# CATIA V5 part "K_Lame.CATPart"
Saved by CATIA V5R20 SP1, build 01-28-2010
Part number: lame
Bounding box of the stored display mesh (mm): x 0 to 3, y -5 to 5, z 0 to 19.99
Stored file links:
  G:\Khaled_CFAO_2011\SIL\SIL_GR1\mroland\Khaled\CAD_CATIA_Modifie\K_Lame.CATPart
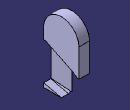
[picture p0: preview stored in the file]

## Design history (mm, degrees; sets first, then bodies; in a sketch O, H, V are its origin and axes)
Set1
  Sketch1 on yz-plane, origin (0, 0, 0), H (0, 1, 0), V (0, 0, 1)
    point P1 (-5, 15)
    line L1 (-5, 15) -> (-5, 0)
    line L2 (-5, 0) -> (5, 0)
    line L3 (5, 0) -> (5, 15)
    arc A1 centre (0, 15) radius 5 from (5, 15) to (-5, 15) ccw
    point P6 (0, 20)
    point P7 (-5, 15)
    radius A1 = 5
    length L1 = 15
    vertical: L1 V, L3 V
    horizontal: L2 H
    coincidence: A1 P6, P6 V, P7 L1, P1 P7, L2 H
    tangency: A1 L1, L3 A1
    symmetry: L1 L3 V
  Plane1: type Angle, RefPlane end face of Pocket2, Direction Z axis, Angle 10
Body1 (main body)
  Pad1: profile Sketch1, direction (1, 0, 0), length 3
  Sketch2 on end face of Pad1, origin (3, 0, 0), H (0, 1, 0), V (0, 0, 1)
    line L1 (5, 7) -> (3.2012, 7.8742)
    line L2 (3.2012, 7.8742) -> (0, 0)
    line L3 (0, 0) -> (5, 0)
    line L4 (5, 0) -> (5, 7)
    reference projected line E1 (5, 30.0834) -> (5, 45.1891) from edge [face of Pad1 from Sketch1.L3 | end face of Pad1]
    reference projected line E2 (-4.9509, 0) -> (5.048, 0) from edge [face of Pad1 from Sketch1.L2 | end face of Pad1]
    length L3 = 5
    length L4 = 7
    length L2 = 8.5
    length L1 = 2
    horizontal: L3 H
    vertical: L4 V
    coincidence: L4 E1, L3 E2
  Pocket1: profile Sketch2, direction (-1, 0, 0), through (limit type 3)
  Sketch3 on end face of Pad1, origin (3, 0, 0), H (0, 1, 0), V (0, 0, 1)
    line L1 (3.2012, 7.8742) -> (-5, 11.8596)
    line L2 (-5, 11.8596) -> (-5, 1.2)
    point P3 (-5, 1.2)
    line L3 (-5, 1.2) -> (0, 0)
    point P4 (0, 0)
    line L4 (0, 0) -> (3.2012, 7.8742)
    reference projected line E1 (-5, 45.0834) -> (-5, 30.0834) from edge [face of Pad1 from Sketch1.L1 | end face of Pad1]
    reference projected line E2 (13.7034, 33.7075) -> (10.5023, 25.8333) from edge [end face of Pad1 | face of Pocket1 from Sketch2.L2]
    reference projected line E3 (-6.7877, 12.7284) -> (-8.5865, 13.6026) from edge [end face of Pad1 | face of Pocket1 from Sketch2.L1]
    reference projected line E4 (-4.9509, 0) -> (5.048, 0) from edge [face of Pad1 from Sketch1.L2 | end face of Pad1]
    reference projected line E5 (-4.9509, 0) -> (5.048, 0) from edge [face of Pad1 from Sketch1.L2 | end face of Pad1]
    distance P3 E4 = 1.2
    coincidence: L2 E1, L4 E2, L1 E3, P4 E5
  Pocket2: profile Sketch3, direction (-1, 0, 0), length 2
  Sketch4 on Plane1, origin (0, 0, 0), H (0.1736, -0.9848, 0), V (0, 0, 1)
    line L1 (5.0977, 11.8596) -> (-3.1239, 7.8026)
    line L2 (-3.1239, 7.8026) -> (0.0154, -0.0386)
    line L3 (0.0154, -0.0386) -> (5.0977, 1.2)
    line L4 (5.0977, 1.2) -> (5.0977, 11.8596)
    reference projected line E1 (5.0977, 11.8596) -> (5.0977, 1.2) from edge [face of Pad1 from Sketch1.L1 | end face of Pocket2]
    reference projected line E2 (5.0739, 11.8479) -> (-3.0779, 7.8253) from edge [face of Pocket2 | end face of Pocket2]
    reference projected line E3 (0.092, -0.0199) -> (5.0698, 1.1932) from edge [face of Pocket2 from Sketch3.L3 | end face of Pocket2]
    reference projected line E4 (0, 0) -> (-3.1576, 7.8868) from edge [start face of Pad1 | face of Pocket1 from Sketch2.L2]
    vertical: L4 V
    coincidence: L4 E1, L1 E2, L3 E3, L2 E4
  Pocket3: profile Sketch4, direction (0.9848, 0.1736, 0), length 10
